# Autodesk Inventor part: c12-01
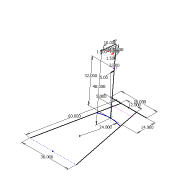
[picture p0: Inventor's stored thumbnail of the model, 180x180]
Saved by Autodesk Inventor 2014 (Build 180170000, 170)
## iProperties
Created: 2010-12
Part Number: c12-01
Material: Generic
Document SubType Name: Modeling
Designer: Thom Tremblay
Density: 1 g/cm^3
Appearance: Generic
Author: Thom Tremblay
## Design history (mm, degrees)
sketch "Sketch1"
  geometry: L1 (355.6, 0)-(-355.6, 0); L2 (152.4, 0)-(457.2, 1493.209); L3 (-152.4, 0)-(-457.2, 1493.209); L4 (224.987, 355.6)-(-224.987, 355.6); L5 (457.2, 1493.209)-(-457.2, 1493.209); L6 (-178.324, 127)-(178.324, 127); A1 r 609.6 centre (0, 965.2) between (-234.567, 402.536) and (234.567, 402.536); 4 further points
  constraints: 12 end point, 8 point on line, 3 midpoint, 3 parallel, 2 point on circle, 2 vertical alignment, 1 centre point, 1 coincident, 1 equal length, 1 horizontal, 1 horizontal alignment, 1 tangent
  dimensions: "d0" = 711.2 distance of L1.start L1.end; "d1" = 1524 distance of L2.start L2.end; "d2" = 304.8 distance of L3.start L2.start; "d3" = 355.6 distance between parallel lines of L1 L4; "d4" = 914.4 distance of L2.end L3.end; "d8" = 127 distance between parallel lines of L6 L1; "d19" = 609.6 radius of A1
sketch "Sketch2"
  geometry: L1 (1189.698, 402.31)-(1193.209, 442.435); L2 (1214.561, 249.34)-(1236.698, 502.373); L3 (1086.772, 306.233)-(1180.722, 385.066); L4 (1028.106, 303.898)-(1068.232, 300.387); L5 (0, 355.6)-(348.79, 355.6); L6 (0, 355.6)-(1214.561, 249.34); A1 r 25.4 centre (1164.395, 404.523) between (1180.722, 385.066) and (1189.698, 402.31); A2 r 25.4 centre (1070.446, 325.691) between (1068.232, 300.387) and (1086.772, 306.233); 4 further points
  constraints: 12 end point, 4 point on circle, 4 point on line, 4 tangent, 2 centre point, 1 coincident, 1 equal radius, 1 horizontal, 1 perpendicular
  dimensions: "d20" = 254 distance of L2.start L2.end; "d21" = 50.8 distance of point (1188.781, 391.829) L1.end; "d22" = 38.1 distance between parallel lines of L2 L1; "d23" = 45 deg angle of L3 L4; "d24" = 1219.2 distance of L5.start L2.start; "d25" = 5 deg angle of L6 L5; "d26" = 152.4 distance from line of L4.start L1; "d28" = 38.1 distance between parallel lines of L6 L4; "d29" = 25.4 radius of A2
workplane "Work Plane1"
sketch "Sketch3"
  geometry: L1 (812.8, -38.1)-(812.8, 38.1); L2 (0, 0)-(1219.2, 0) reference; 3 further points
  constraints: 2 end point, 1 midpoint, 1 point on line, 1 vertical
  dimensions: "d9" = 76.2 distance of L1.start L1.end; "d10" = 812.8 distance from line of point (0, 0) L1
